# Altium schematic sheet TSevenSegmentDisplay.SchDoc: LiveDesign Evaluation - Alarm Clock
size A2; Organization: Altium Limited; Address1: L3, 12a Rodborough Rd; Address2: Frenchs Forest; Address3: NSW; Address4: Australia 2086; DocumentNumber: 9; SheetNumber: 9; SheetTotal: 10
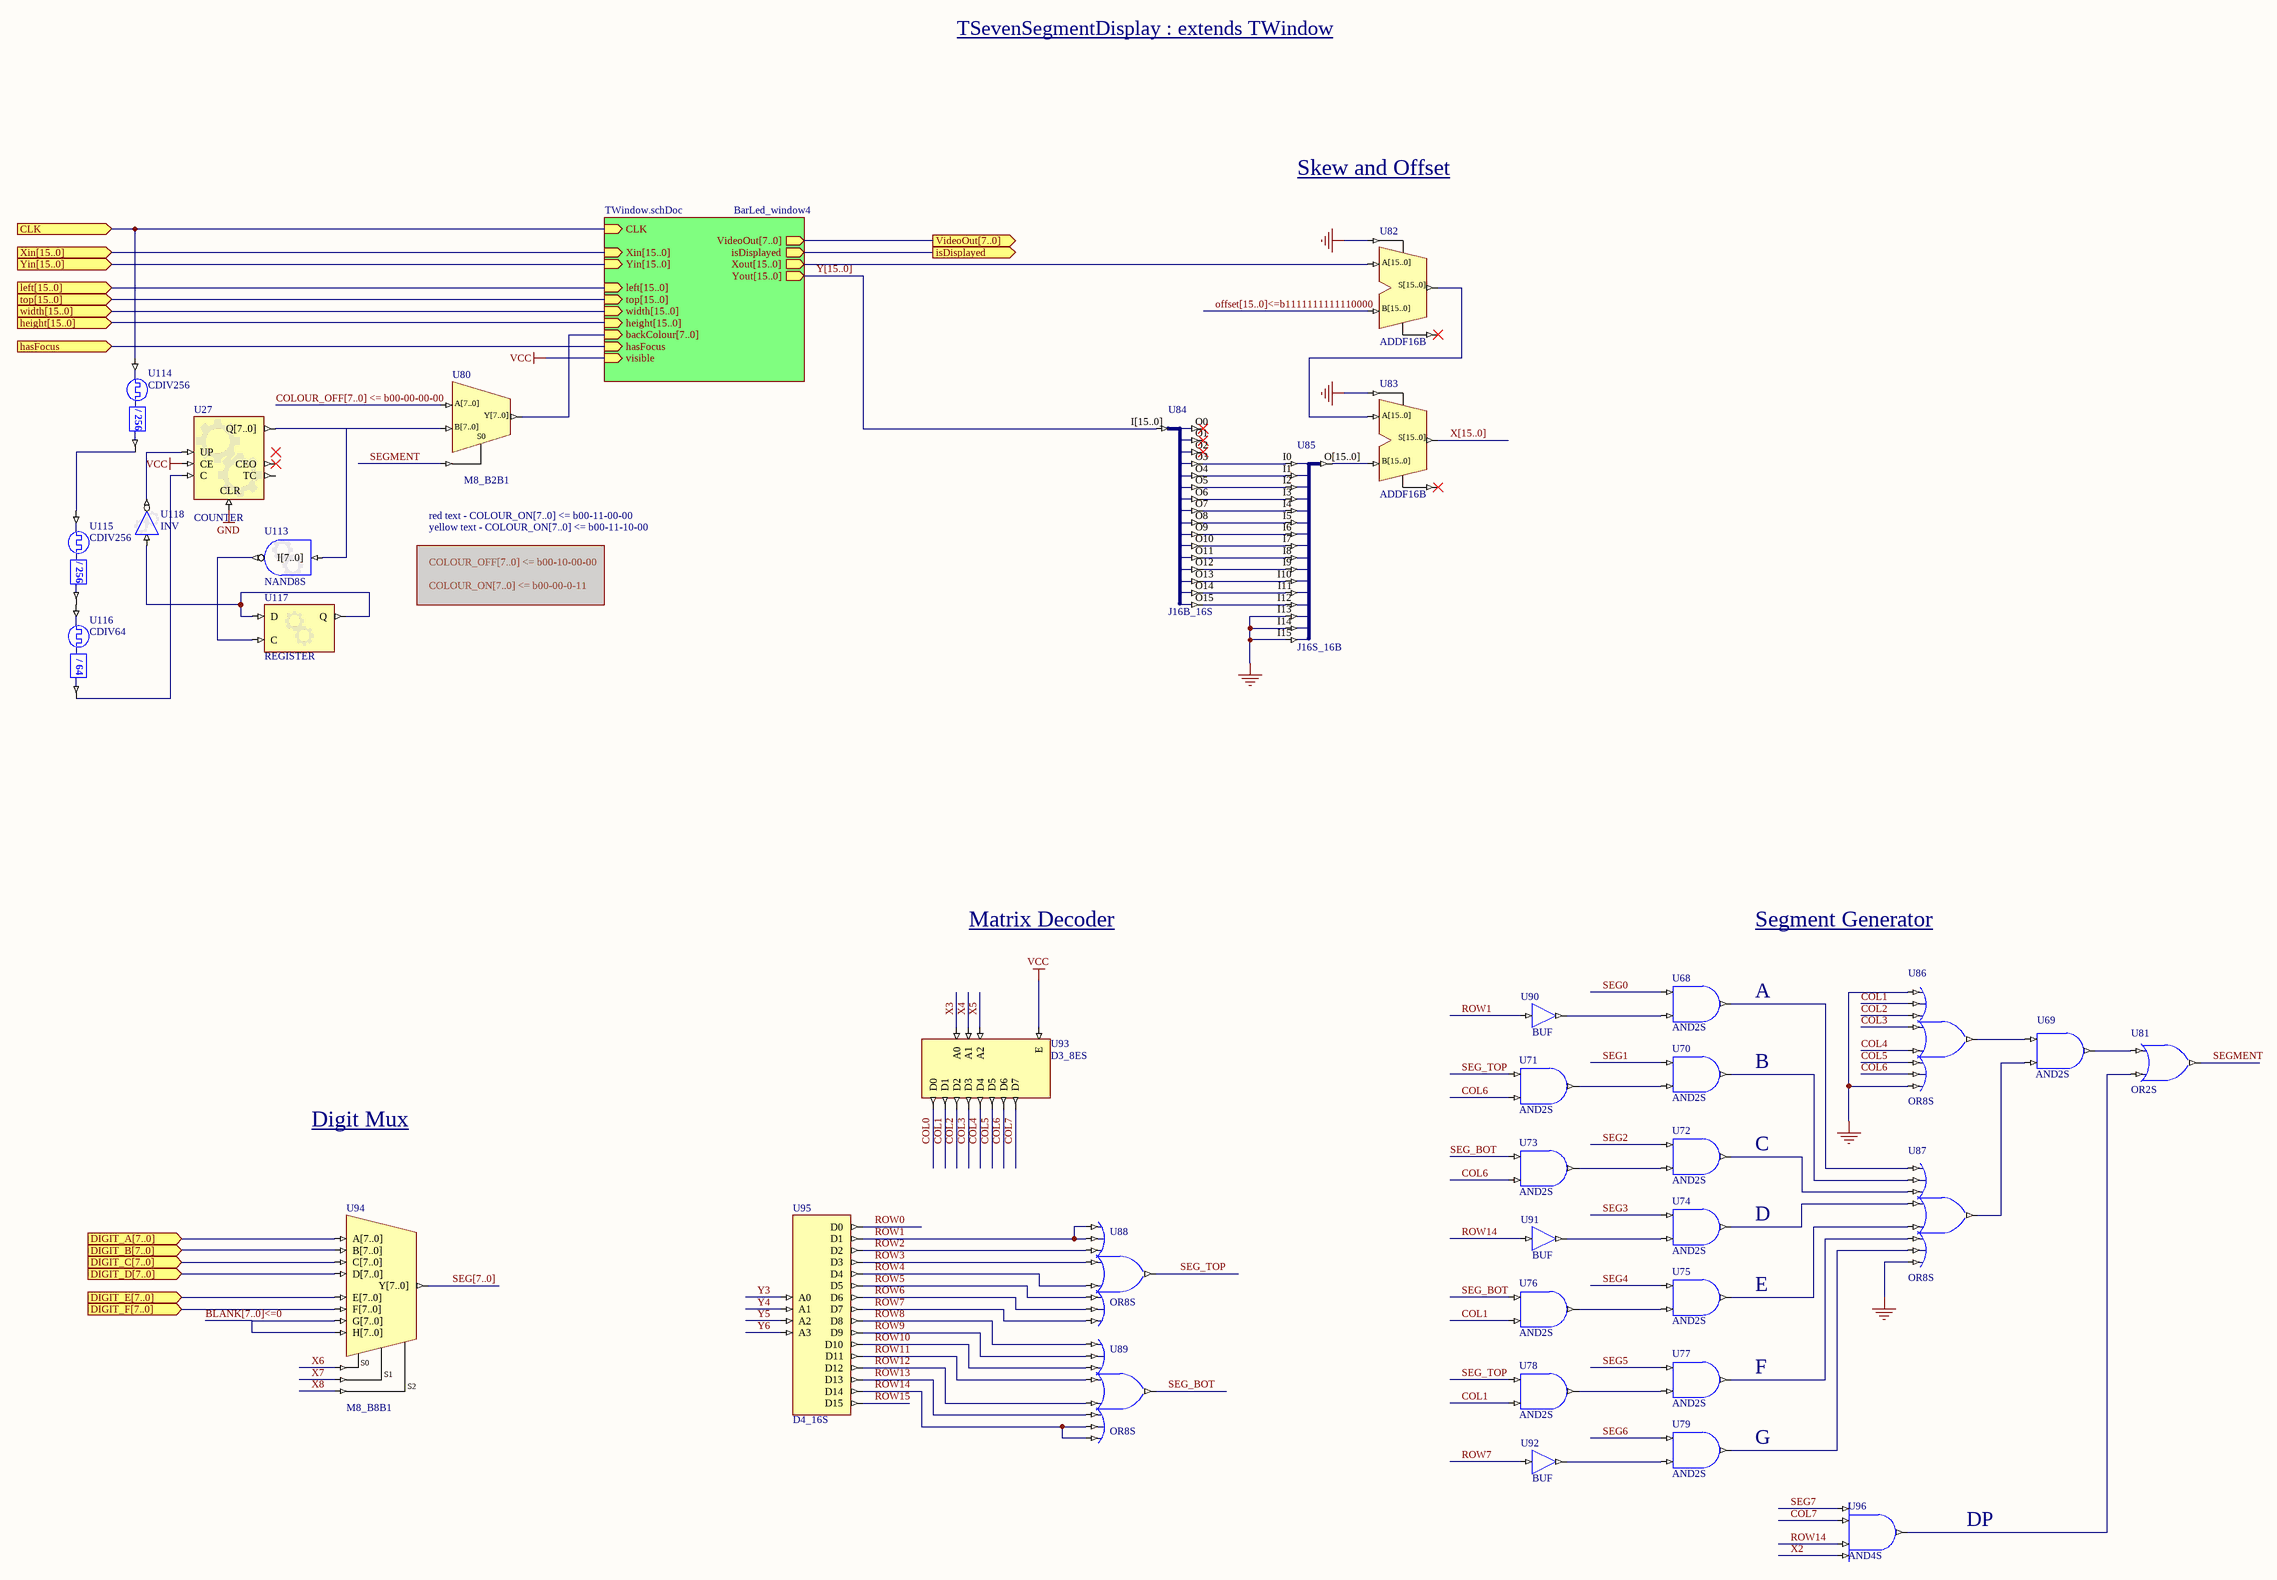
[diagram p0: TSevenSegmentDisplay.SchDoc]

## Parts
U27  COUNTER
U68  AND2S
U69  AND2S
U70  AND2S
U71  AND2S
U72  AND2S
U73  AND2S
U74  AND2S
U75  AND2S
U76  AND2S
U77  AND2S
U78  AND2S
U79  AND2S
U80  M8_B2B1
U81  OR2S
U82  ADDF16B
U83  ADDF16B
U84  J16B_16S
U85  J16S_16B
U86  OR8S
U87  OR8S
U88  OR8S
U89  OR8S
U90  BUF
U91  BUF
U92  BUF
U93  D3_8ES
U94  M8_B8B1
U95  D4_16S
U96  AND4S
U113  NAND8S
U114  CDIV256
U115  CDIV256
U116  CDIV64
U117  REGISTER
U118  INV

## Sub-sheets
BarLed_window4 = TWindow.schDoc: CLK (in), VideoOut[7..0] (out), Xin[15..0] (in), Yin[15..0] (in), top[15..0] (in), width[15..0] (in), height[15..0] (in), left[15..0] (in), Xout[15..0] (out), Yout[15..0] (out), backColour[7..0] (in), isDisplayed (out), visible (in), hasFocus (in)

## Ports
CLK (in), DIGIT_A[7..0] (in), DIGIT_B[7..0] (in), DIGIT_C[7..0] (in), DIGIT_D[7..0] (in), DIGIT_E[7..0] (in), DIGIT_F[7..0] (in), hasFocus (in), height[15..0] (in), isDisplayed (out), left[15..0] (in), top[15..0] (in), VideoOut[7..0] (out), width[15..0] (in), Xin[15..0] (in), Yin[15..0] (in)

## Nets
GND: U27.CLR U82.CI U83.CI U85.I13 U85.I14 U85.I15 U86.I0 U86.I7 U87.I7
VCC: U27.CE U93.E ; sheet BarLed_window4/visible
CLK: U114.CLKIN ; port CLK, sheet BarLed_window4/CLK
COL0: U93.D0
COL1: U76.I1 U78.I1 U86.I1 U93.D1
COL2: U86.I2 U93.D2
COL3: U86.I3 U93.D3
COL4: U86.I4 U93.D4
COL5: U86.I5 U93.D5
COL6: U71.I1 U73.I1 U86.I6 U93.D6
COL7: U93.D7 U96.I1
hasFocus: port hasFocus, sheet BarLed_window4/hasFocus
isDisplayed: port isDisplayed, sheet BarLed_window4/isDisplayed
ROW0: U95.D0
ROW1: U88.I0 U88.I1 U90.I U95.D1
ROW2: U88.I2 U95.D2
ROW3: U88.I3 U95.D3
ROW4: U88.I4 U95.D4
ROW5: U88.I5 U95.D5
ROW6: U88.I6 U95.D6
ROW7: U88.I7 U92.I U95.D7
ROW8: U89.I0 U95.D8
ROW9: U89.I1 U95.D9
ROW10: U89.I2 U95.D10
ROW11: U89.I3 U95.D11
ROW12: U89.I4 U95.D12
ROW13: U89.I5 U95.D13
ROW14: U89.I6 U89.I7 U91.I U95.D14 U96.I2
ROW15: U95.D15
SEG0: U68.I0
SEG1: U70.I0
SEG2: U72.I0
SEG3: U74.I0
SEG4: U75.I0
SEG5: U77.I0
SEG6: U79.I0
SEG7: U96.I0
SEG_BOT: U73.I0 U76.I0 U89.O
SEG_TOP: U71.I0 U78.I0 U88.O
SEGMENT: U80.S0 U81.O
X2: U96.I3
X3: U93.A0
X4: U93.A1
X5: U93.A2
X6: U94.S0
X7: U94.S1
X8: U94.S2
Y3: U95.A0
Y4: U95.A1
Y5: U95.A2
Y6: U95.A3
NetU27_C: U27.C U116.CLKDV
NetU27_UP: U27.UP U118.O
NetU68_I1: U68.I1 U90.O
NetU68_O: U68.O U87.I0
NetU69_I0: U69.I0 U86.O
NetU69_I1: U69.I1 U87.O
NetU69_O: U69.O U81.I0
NetU70_I1: U70.I1 U71.O
NetU70_O: U70.O U87.I1
NetU72_I1: U72.I1 U73.O
NetU72_O: U72.O U87.I2
NetU74_I1: U74.I1 U91.O
NetU74_O: U74.O U87.I3
NetU75_I1: U75.I1 U76.O
NetU75_O: U75.O U87.I4
NetU77_I1: U77.I1 U78.O
NetU77_O: U77.O U87.I5
NetU79_I1: U79.I1 U92.O
NetU79_O: U79.O U87.I6
NetU81_I1: U81.I1 U96.O
NetU84_O3: U84.O3 U85.I0
NetU84_O4: U84.O4 U85.I1
NetU84_O5: U84.O5 U85.I2
NetU84_O6: U84.O6 U85.I3
NetU84_O7: U84.O7 U85.I4
NetU84_O8: U84.O8 U85.I5
NetU84_O9: U84.O9 U85.I6
NetU84_O10: U84.O10 U85.I7
NetU84_O11: U84.O11 U85.I8
NetU84_O12: U84.O12 U85.I9
NetU84_O13: U84.O13 U85.I10
NetU84_O14: U84.O14 U85.I11
NetU84_O15: U84.O15 U85.I12
NetU113_O: U113.O U117.C
NetU114_CLKDV: U114.CLKDV U115.CLKIN
NetU115_CLKDV: U115.CLKDV U116.CLKIN
NetU117_D: U117.D U117.Q U118.I

Not connected (* = marked no-connect by the designer): U27 CEO* Q[7..0] TC; U80 A[7..0] B[7..0] Y[7..0]; U82 A[15..0] B[15..0] CO* S[15..0]; U83 A[15..0] B[15..0] CO* S[15..0]; U84 I[15..0] O0* O1* O2*; U85 O[15..0]; U94 A[7..0] B[7..0] C[7..0] D[7..0] E[7..0] F[7..0] G[7..0] H[7..0] Y[7..0]; U113 I[7..0]

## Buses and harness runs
bus BLANK[7..0]<=0
bus COLOUR_OFF[7..0] <= b00-00-00-00
bus offset[15..0]<=b1111111111110000
bus port height[15..0] = sheet BarLed_window4/height[15..0]
bus port left[15..0] = sheet BarLed_window4/left[15..0]
bus port top[15..0] = sheet BarLed_window4/top[15..0]
bus port VideoOut[7..0] = sheet BarLed_window4/VideoOut[7..0]
bus port width[15..0] = sheet BarLed_window4/width[15..0]
bus port Xin[15..0] = sheet BarLed_window4/Xin[15..0]
bus port Yin[15..0] = sheet BarLed_window4/Yin[15..0]
bus SEG[7..0]
bus X[15..0]
bus Y[15..0] = sheet BarLed_window4/Yout[15..0]

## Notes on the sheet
- TSevenSegmentDisplay : extends TWindow
- Skew and Offset
- yellow text - COLOUR_ON[7..0] <= b00-11-10-00
- red text - COLOUR_ON[7..0] <= b00-11-00-00
- Matrix Decoder
- Segment Generator
- (near U68) A
- B
- Digit Mux
- (near U72) C
- D
- E
- (near U77) F
- G
- DP

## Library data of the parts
U27 = COUNTER: Configurable Counter; ConfiguratorName: GENERIC_COUNTER; ConfigurationParameters: {}Version[1.0]{}Type[Binary]{}SyncReset[False]{}NegativeClockEdge[False]{}FixedDirection[False]{}IsIncrement[False]{}SignalWidth[8]{}MaxValue[255]{}BusOutput[True]{}Loadable[False]{}BusInput[False]{}ShowPinNames[True]{}
U68-U79 = AND2S: 2-Input AND Gate, Single Pin Version; Xilinx Equivalent: AND2; ArchiveName: GENERIC; VHDLIB_SIM: GENERIC_LIB
U80 = M8_B2B1: 2x8-Bit Bus to 1x8-Bit Bus Multiplexer; ArchiveName: GENERIC; VHDLIB_SIM: GENERIC_LIB
U81 = OR2S: 2-Input OR Gate, Single Pin Version; Xilinx Equivalent: OR2; ArchiveName: GENERIC; VHDLIB_SIM: GENERIC_LIB
U82 U83 = ADDF16B: 16-Bit Cascadable Unsigned Binary Full Adder, Bus Version; ArchiveName: GENERIC; VHDLIB_SIM: GENERIC_LIB
U84 = J16B_16S: Single 16-Bit input bus to 16 single pin outputs; ArchiveName: GENERIC; VHDLIB_SIM: GENERIC_LIB
U85 = J16S_16B: 16 Single pin inputs to single 16-Bit output bus; ArchiveName: GENERIC; VHDLIB_SIM: GENERIC_LIB
U86-U89 = OR8S: 8-Input OR Gate, Single Pin Version; Xilinx Equivalent: OR8; ArchiveName: GENERIC; VHDLIB_SIM: GENERIC_LIB
U90-U92 = BUF: 1-bit General Purpose (Non-inverting) Buffer; ArchiveName: GENERIC; VHDLIB_SIM: GENERIC_LIB
U93 = D3_8ES: Binary 3- to 8-Bit Decoder with Enable, Single Pin Version; Xilinx Equivalent: D3_8E; ArchiveName: GENERIC; VHDLIB_SIM: GENERIC_LIB
U94 = M8_B8B1: 8x8-Bit Bus to 1x8-Bit Bus Multiplexer; ArchiveName: GENERIC; VHDLIB_SIM: GENERIC_LIB
U95 = D4_16S: Binary 4- to 16-Bit Decoder, Single Pin Version; ArchiveName: GENERIC; VHDLIB_SIM: GENERIC_LIB
U96 = AND4S: 4-Input AND Gate, Single Pin Version; Xilinx Equivalent: AND4; ArchiveName: GENERIC; VHDLIB_SIM: GENERIC_LIB
U113 = GATE: Configurable Generic Gate; ConfiguratorName: GENERIC_GATE; ConfigurationParameters: {}Version[1.1]{}GateKind[NAND]{}BusInput[True]{}GateInputType[Bit]{}GateOutputOption[Normal]{}BusWidth[8]{}RegisterOutputs[False]{}NegativeClockEdge[False]{}InputCount[8]{}InputInvert0[False]{}InputInvert1[False]{}InputInvert2[False]{}InputInvert3[False]{}InputInvert4[False]{}InputInvert5[False]{}InputInvert6[False]{}InputInvert7[False]{}
U114 U115 = CDIV256: Clock Divider by 256; DivisorRate: 256; ArchiveName: GENERIC; VHDLIB_SIM: GENERIC_LIB
U116 = CDIV64: Clock Divider by 64; DivisorRate: 64; ArchiveName: GENERIC; VHDLIB_SIM: GENERIC_LIB
U117 = REGISTER: Configurable Register; ConfiguratorName: GENERIC_REGISTER; ConfigurationParameters: {}Version[1.1]{}RegisterType[DFlipFlop]{}NegativeTrigger[False]{}TriggerEnable[False]{}ResetMode[None]{}SetMode[None]{}SignalCount[1]{}SignalWidth0[1]{}OutputOption0[Normal]{}
U118 = INV: Configurable Inverter; ConfigurationParameters: {}Version[1.1]{}SignalCount[1]{}SignalWidth0[1]{}OutputOption0[Inverted]{}EnableMode[None]{}ShowPinNames[False]{}; ConfiguratorName: GENERIC_BUFFER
